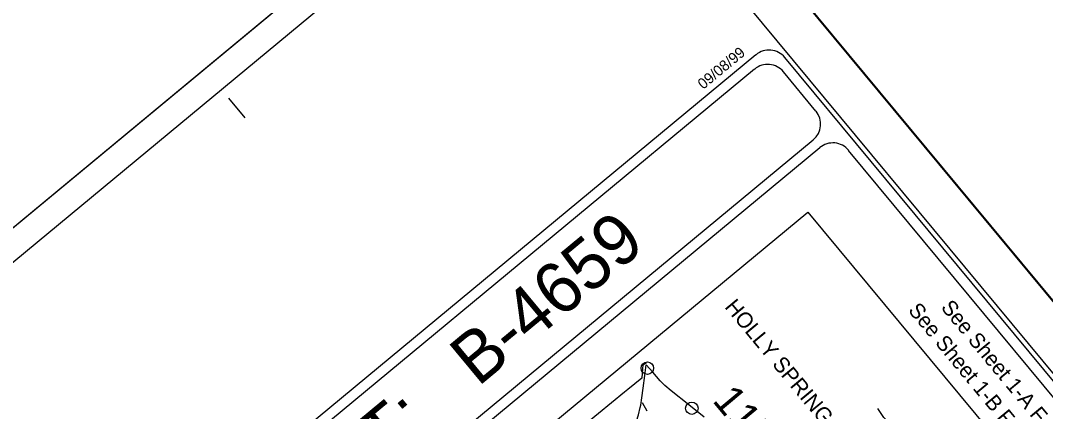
# Model space of a CAD drawing. Extents: x 2054826 to 2060231, y 685508 to 690809.
# Drawn here: x 2058198 to 2058951, y 689821 to 690109 of the extents above; entities that cross this region are included whole.
import ezdxf

# ---------------------------------------------------------------- set-up
doc = ezdxf.new("R2010")
doc.units = 0
for name, color, linetype in [('Default', 7, 'Continuous'), ('Old_Level_10', 7, 'Continuous'), ('Old_Level_32', 7, 'Continuous'), ('Old_Level_56', 7, 'Continuous'), ('Old_Level_59', 7, 'Continuous'), ('Old_Level_8', 7, 'Continuous'), ('Prop Dimension Text', 7, 'Continuous'), ('Sheet Cutting Line CELL', 7, 'Continuous'), ('Sheet Plot Border Inside CELL', 7, 'Continuous'), ('Sheet Plot Border Outside CELL', 7, 'Continuous'), ('Sheet Title CELL', 7, 'Continuous')]:
    doc.layers.add(name, color=color, linetype=linetype)

msp = doc.modelspace()

# ---------------------------------------------------------------- linework, layer by layer
at = {"layer": 'Default'}
msp.add_lwpolyline([(2058776.37, 689968.05), (2059134.67, 689535.97), (2058721.62, 689193.45), (2058363.32, 689625.52)], close=True, dxfattribs=at)
for centre in [(2058658.6, 689853.25), (2058691.27, 689823.81)]:
    msp.add_circle(centre, 4.59, dxfattribs=at)
at = {"layer": 'Old_Level_10'}
msp.add_line((2058658.34, 689821.77), (2058654.98, 689827.76), dxfattribs=at)
at = {"layer": 'Old_Level_32'}
for points in [[(2058653.3, 689824.33), (2058653.71, 689826.12), (2058654.51, 689831.46), (2058655.55, 689838.62), (2058656.8, 689847.88), (2058657.69, 689855.78)], [(2058700.32, 689817.33), (2058689.1, 689826.26), (2058675.97, 689836.68), (2058671.28, 689840.57), (2058668.04, 689843.88), (2058662.47, 689850.46), (2058657.69, 689855.78)], [(2058679.59, 689634.33), (2058678.7, 689638.67), (2058676.93, 689646.07), (2058675.26, 689651.03), (2058672.43, 689657.49), (2058665.7, 689670.57), (2058655.97, 689688.24), (2058649.78, 689699.24), (2058645.72, 689707.22), (2058642.52, 689716.04), (2058640.32, 689723.55), (2058638.82, 689731.26), (2058636.85, 689748.06), (2058636.51, 689755.34), (2058636.4, 689760.19), (2058636.96, 689764.8), (2058637.85, 689768.69), (2058640.76, 689779.82), (2058643.98, 689790.93), (2058649.46, 689810.49), (2058652.07, 689818.96), (2058653.3, 689824.33)]]:
    msp.add_lwpolyline(points, dxfattribs=at)
at = {"layer": 'Old_Level_56'}
for p, q in [((2058641.86, 689835.6), (2058602.32, 689803.39)), ((2058641.88, 689835.62), (2058641.86, 689835.6)), ((2058644.28, 689837.58), (2058641.88, 689835.62))]:
    msp.add_line(p, q, dxfattribs=at)
for points in [[(2058658, 689857.25), (2058655.34, 689855.6), (2058655.11, 689852.96)], [(2058655.11, 689852.96), (2058654.49, 689845.89), (2058644.28, 689837.58)]]:
    msp.add_lwpolyline(points, dxfattribs=at)
at = {"layer": 'Old_Level_59'}
msp.add_lwpolyline([(2058845.09, 689749.43), (2058845.24, 689749.98), (2058846.03, 689751.67), (2058850.9, 689768.02), (2058851.51, 689775.27), (2058849.4, 689781.98), (2058850.2, 689788.66), (2058848.74, 689795.92), (2058846.31, 689803.04), (2058832.29, 689817.11), (2058827.84, 689823.74)], dxfattribs=at)
at = {"layer": 'Sheet Cutting Line CELL'}
for q in [(2057348.74, 689256.87), (2060231.25, 688365.67)]:
    msp.add_line((2058618.84, 690310.09), q, dxfattribs=at)
at = {"layer": 'Sheet Plot Border Inside CELL'}
msp.add_lwpolyline([(2057387.09, 689263.34), (2058982.75, 687339.12), (2060201.02, 688349.37), (2058605.36, 690273.59)], close=True, dxfattribs=at)
at = {"layer": 'Sheet Plot Border Outside CELL'}
msp.add_lwpolyline([(2060231.25, 688365.67), (2058618.84, 690310.09), (2057348.74, 689256.87), (2058961.15, 687312.44)], close=True, dxfattribs=at)
at = {"layer": 'Sheet Title CELL'}
for p, q in [((2058350.77, 690051.75), (2058362.74, 690037.32)), ((2058350.77, 690051.75), (2058362.74, 690037.32)), ((2057602.7, 689044.61), (2058780.44, 690021.25)), ((2057821.1, 689215.97), (2058785.23, 690015.48))]:
    msp.add_line(p, q, dxfattribs=at)
for points in [[(2058738.34, 690083.77), (2057549.05, 689097.55)], [(2058738.34, 690083.77), (2057549.05, 689097.55)], [(2060176.54, 688372.89), (2058759.45, 690081.81)], [(2058737.36, 690073.19), (2057559.61, 689096.57)], [(2058782.4, 690042.36), (2058758.47, 690071.24)], [(2060165.97, 688373.89), (2058806.35, 690013.48)]]:
    msp.add_lwpolyline(points, dxfattribs=at)
for centre, start, end in [((2058747.97, 690072.26), 39.66721, 129.66721), ((2058746.98, 690061.7), 39.66721, 129.66721), ((2058770.92, 690032.83), 309.66721, 39.66721), ((2058794.86, 690003.97), 39.66721, 129.66721)]:
    msp.add_arc(centre, 15, start, end, dxfattribs=at)

# ---------------------------------------------------------------- texts
at = {"layer": 'Old_Level_8'}
msp.add_text('1152', height=21.964, rotation=309.90933, dxfattribs=at).set_placement((2058705.77, 689829.15))
at = {"layer": 'Prop Dimension Text'}
msp.add_text('HOLLY SPRINGS', height=11.4912, rotation=309.66721, dxfattribs=at).set_placement((2058714.84, 689898.13))
at = {"layer": 'Sheet Title CELL'}
for s, height, rotation, p in [('09/08/99', 7.875, 39.66721, (2058699.58, 690057.96)), ('B-4659  ', 37.5, 39.66721, (2058534.05, 689839.12)), ('See Sheet 1-A For Index of Sheets', 11.25, 309.66721, (2058873.72, 689897.69)), ('See Sheet 1-B For Conventional Symbols', 11.25, 309.66721, (2058849.68, 689895.6)), ('TIP PROJECT:', 37.5, 39.66721, (2058238.96, 689594.42))]:
    msp.add_text(s, height=height, rotation=rotation, dxfattribs=at).set_placement(p)

doc.saveas('drawing.dxf')
